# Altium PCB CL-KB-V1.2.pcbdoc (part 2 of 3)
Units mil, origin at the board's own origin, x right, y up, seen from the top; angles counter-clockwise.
Board outline 3269.95 x 5989.25 mil, 2 copper layers (Top Layer, Bottom Layer); 76 components, 86 nets, 398 pads, 855 vias.
Unrouted connection lines stored in the file: 1.
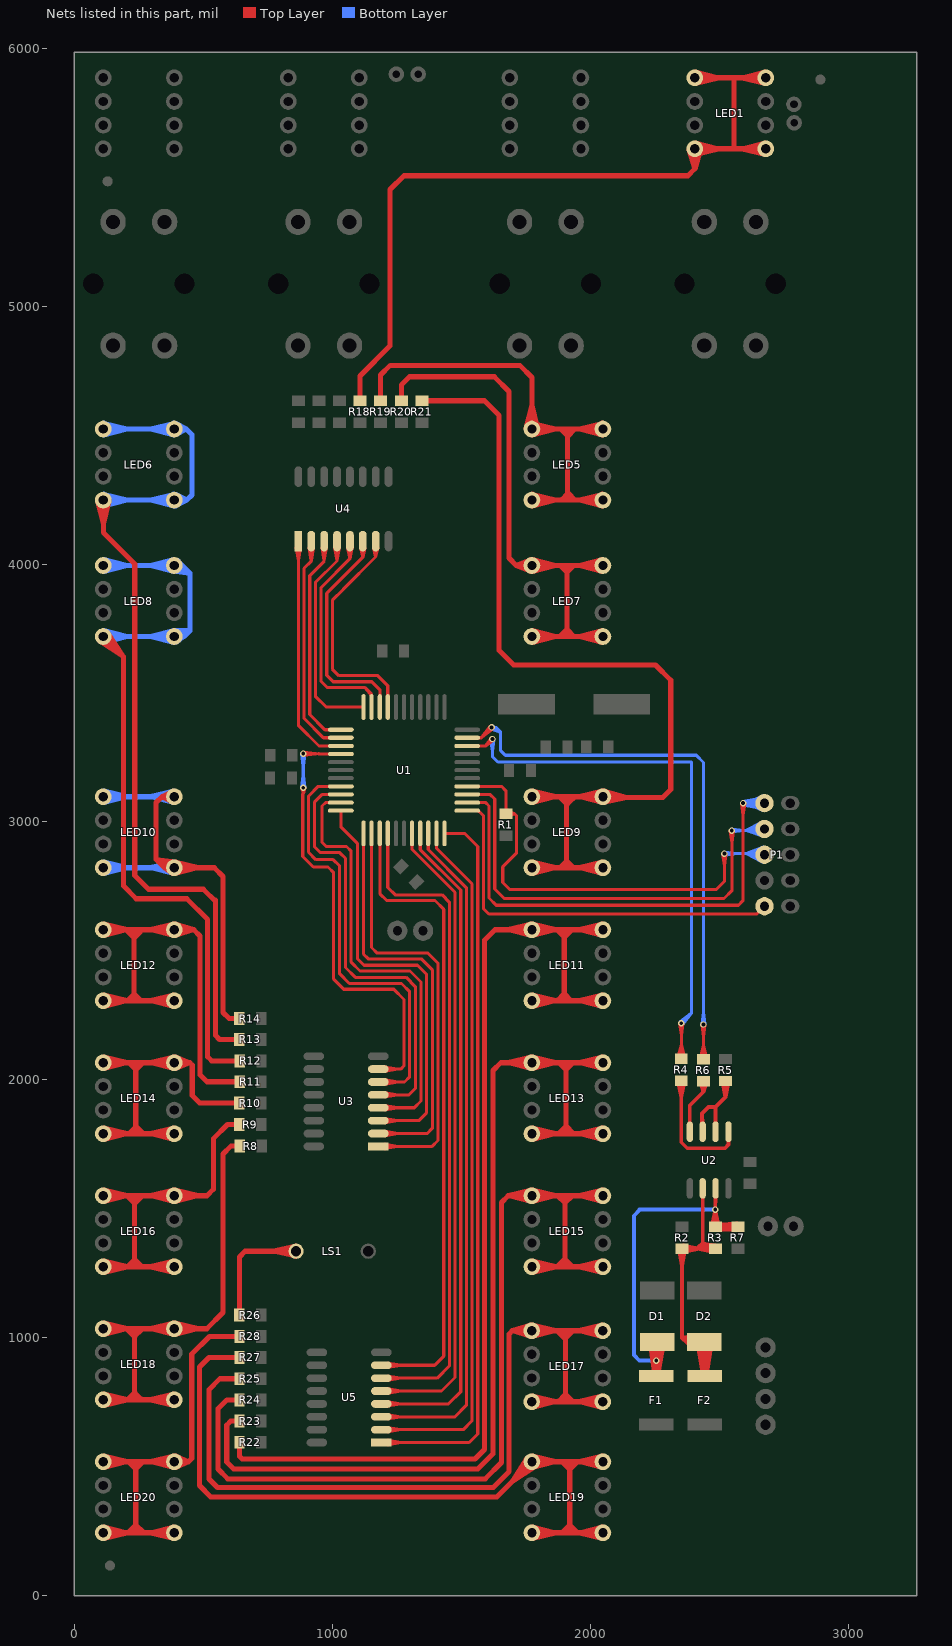
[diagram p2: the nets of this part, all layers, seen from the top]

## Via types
v1: diameter 25, hole 15, Top Layer to Bottom Layer, tented both sides, 855 vias

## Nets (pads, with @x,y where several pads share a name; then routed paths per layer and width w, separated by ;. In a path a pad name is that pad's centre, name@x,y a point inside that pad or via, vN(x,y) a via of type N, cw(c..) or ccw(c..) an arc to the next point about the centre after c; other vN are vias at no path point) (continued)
LEDK4: LED1.K R18.1 | length 4053.9
  Top Layer w20: R18.1@1106.15,4634.52 1106.15,4731.15 1223,4848 1223,5454 1277,5508 2379,5508 2405.48,5534.48 ; LED1.K@2383.22,5608.95 2405.48,5534.48 ; LED1.K@2405.48,5887.8 LED1.K@2681.07,5887.8 ; LED1.K@2408.22,5589.87 2497.98,5612.2 LED1.K@2408.22,5634.54 ; LED1.K@2408.22,5865.46 2497.98,5887.8 LED1.K@2408.22,5910.13 ; LED1.K@2427.74,5608.95 2405.48,5534.48 ; 2557,5612.2 2557,5887.8 ; LED1.K@2678.33,5589.87 2588.57,5612.2 ; LED1.K@2678.33,5634.54 2588.57,5612.2 ; LED1.K@2678.33,5865.46 2588.57,5887.8 LED1.K@2678.33,5910.13 ; 2405.48,5534.48 LED1.K@2405.48,5612.2 ; 2405.48,5534.48 LED1.K@2405.48,5612.2 ; LED1.K@2405.48,5612.2 LED1.K@2681.07,5612.2 2588.57,5612.2
LEDK5: LED5.K R19.1 | length 2998.3
  Top Layer w20: R19.1@1185.88,4634.52 1185.88,4734 1223.88,4772 1726,4772 1773.2,4724.8 LED5.K@1773.2,4524.8 LED5.K@2048.79,4524.8 1956.29,4524.8 ; LED5.K@1750.86,4527.54 1773.2,4617.3 LED5.K@1795.53,4527.54 ; LED5.K@1773.2,4249.21 LED5.K@2048.79,4249.21 1956.29,4249.21 ; LED5.K@1775.93,4226.88 1865.7,4249.21 LED5.K@1775.93,4271.54 ; LED5.K@1775.93,4502.47 1865.7,4524.8 LED5.K@1775.93,4547.14 ; 1886,4524.8 1911,4499.8 ; 1888.8,4250.21 1913.8,4275.21 ; 1912,4249.21 1912,4522.8 ; 1912.8,4498 1937.8,4523 ; 1914.8,4274.41 1939.8,4249.41 ; LED5.K@2046.05,4226.88 1956.29,4249.21 ; LED5.K@2046.05,4271.54 1956.29,4249.21 ; LED5.K@2046.05,4502.47 1956.29,4524.8 ; LED5.K@2046.05,4547.14 1956.29,4524.8
LEDK6: LED7.K R20.1 | length 3338.5
  Top Layer w20: R20.1@1266.58,4634.52 1266.58,4696 1298.58,4728 1627,4728 1684,4671 1684,4024 1712.72,3995.28 ; LED7.K@1769.01,3973.17 1712.72,3995.28 ; LED7.K@1769.01,4017.38 1712.72,3995.28 ; LED7.K@1773.2,3719.68 LED7.K@2048.79,3719.68 1956.29,3719.68 ; LED7.K@1773.2,3995.28 1712.72,3995.28 ; LED7.K@1775.93,3697.35 1865.7,3719.68 LED7.K@1775.93,3742.02 ; LED7.K@1775.93,3972.94 1865.7,3995.28 LED7.K@1775.93,4017.61 ; 1884,3994.8 1909,3969.8 ; 1884.2,3723 1909.2,3748 ; 1910,3719.68 1910,3995.28 ; 1910,3970 1935,3995 ; 1911,3745.2 1936,3720.2 ; LED7.K@2046.05,3697.35 1956.29,3719.68 ; LED7.K@2046.05,3742.02 1956.29,3719.68 ; LED7.K@2046.05,3972.94 1956.29,3995.28 ; LED7.K@2046.05,4017.61 1956.29,3995.28 ; 1712.72,3995.28 LED7.K@2048.79,3995.28 1956.29,3995.28
LEDK7: LED9.K R21.1 | length 4901.7
  Top Layer w20: R21.1@1346.31,4634.52 1589.48,4634.52 1646,4578 1646,3666 1703,3609 2253,3609 2312,3550 2312,3126 2281,3095 2051.82,3095 LED9.K@2048.79,3098.03 ; R21.1@1351.31,4634.52 1431.31,4634.52 ; LED9.K@1773.2,2822.44 LED9.K@2048.79,2822.44 1956.29,2822.44 ; LED9.K@1773.2,3098.03 LED9.K@2048.79,3098.03 ; LED9.K@1775.93,2800.11 1865.7,2822.44 LED9.K@1775.93,2844.77 ; LED9.K@1775.93,3075.7 1865.7,3098.03 LED9.K@1775.93,3120.36 ; 1882,3097.23 1907,3072.23 ; 1883.8,2823.44 1908.8,2848.44 ; 1908,2822.44 1908,3098.03 ; 1908.8,3067 1933.8,3092 ; 1909.8,2847.64 1934.8,2822.64 ; LED9.K@2046.05,2800.11 1956.29,2822.44 ; LED9.K@2046.05,2844.77 1956.29,2822.44 ; LED9.K@2046.05,3075.7 1956.29,3098.03 ; LED9.K@2046.05,3120.36 1956.29,3098.03 ; LED9.K@2050.79,3075.62 2141.4,3095 ; LED9.K@2052.25,3120.26 2141.4,3095 ; 1956.29,3098.03 LED9.K@2048.79,3098.03 ; LED9.K@2048.79,3098.03 2141.4,3095
LEDK8: LED18.K R8.1 | length 3022
  Top Layer w20: LED18.K@110.2,757.87 LED18.K@385.8,757.87 293.3,757.87 ; LED18.K@110.2,1033.46 511.46,1033.46 574,1096 574,1711 605,1742 ; LED18.K@112.94,735.54 202.7,757.87 LED18.K@112.94,780.21 ; LED18.K@112.94,1011.13 202.7,1033.46 LED18.K@112.94,1055.8 ; 205,1028.8 230,1003.8 ; 206.2,759.2 231.2,784.2 ; 229,1033.46 231,1031.46 231,757.87 ; 231.8,1004 256.8,1029 ; 232,785.2 257,760.2 ; LED18.K@383.06,735.54 293.3,757.87 ; LED18.K@383.06,780.21 293.3,757.87 ; LED18.K@383.06,1011.13 293.3,1033.46 ; LED18.K@383.06,1055.8 293.3,1033.46 ; LED18.K@385.8,1033.46 293.3,1033.46 ; LED18.K@388.53,1011.13 478.3,1033.46 LED18.K@388.53,1055.8 ; 605,1742 R8.1@640,1742 605,1742
LEDK9: LED16.K R9.1 | length 2607.3
  Top Layer w20: LED16.K@110.2,1274.02 LED16.K@385.8,1274.02 293.3,1274.02 ; LED16.K@110.2,1549.61 512,1549.61 537,1574.61 537,1771 591.54,1825.54 ; LED16.K@112.94,1251.68 202.7,1274.02 LED16.K@112.94,1296.35 ; LED16.K@112.94,1527.27 202.7,1549.61 LED16.K@112.94,1571.94 ; 205.8,1545.8 230.8,1520.8 ; 206.2,1276.2 231.2,1301.2 ; 227,1549.61 231,1545.61 231,1274.02 ; 231.8,1520 256.8,1545 ; 232,1302.2 257,1277.2 ; LED16.K@383.06,1251.68 293.3,1274.02 ; LED16.K@383.06,1296.35 293.3,1274.02 ; LED16.K@383.06,1527.27 293.3,1549.61 ; LED16.K@383.06,1571.94 293.3,1549.61 ; LED16.K@385.8,1549.61 293.3,1549.61 ; LED16.K@388.53,1527.27 478.3,1549.61 LED16.K@388.53,1571.94 ; 591.54,1825.54 R9.1@637.75,1825.54 591.54,1825.54
LEDK10: LED14.K R10.1 | length 2476.4
  Top Layer w20: LED14.K@110.2,1790.16 LED14.K@385.8,1790.16 293.3,1790.16 ; LED14.K@110.2,2065.75 445.25,2065.75 ; LED14.K@112.94,1767.82 202.7,1790.16 LED14.K@112.94,1812.49 ; LED14.K@112.94,2043.41 202.7,2065.75 LED14.K@112.94,2088.08 ; 210,2065.8 235,2040.8 ; 211.2,1792.2 236.2,1817.2 ; 236,1792.16 236,2065.75 ; 236.8,2039 261.8,2064 ; 237,1818.2 262,1793.2 ; LED14.K@383.06,1767.82 293.3,1790.16 ; LED14.K@383.06,1812.49 293.3,1790.16 ; LED14.K@383.06,2043.41 293.3,2065.75 ; LED14.K@383.06,2088.08 293.3,2065.75 ; LED14.K@385.8,2065.75 293.3,2065.75 ; LED14.K@390.05,2043.65 445.25,2065.75 ; LED14.K@390.05,2087.84 445.25,2065.75 ; 558,1909 R10.1@638,1909 484,1909 455,1938 455,2056 445.25,2065.75
LEDK11: LED12.K R11.1 | length 2934.1
  Top Layer w20: LED12.K@110.2,2306.3 LED12.K@385.8,2306.3 293.3,2306.3 ; LED12.K@110.2,2581.89 461.11,2581.89 ; LED12.K@112.94,2283.97 202.7,2306.3 LED12.K@112.94,2328.63 ; LED12.K@112.94,2559.56 202.7,2581.89 LED12.K@112.94,2604.22 ; 203.8,2575.8 228.8,2550.8 ; 204.2,2306.2 229.2,2331.2 ; 229,2306.3 229,2578.89 ; 229.8,2550 254.8,2575 ; 230,2332.2 255,2307.2 ; LED12.K@383.06,2283.97 293.3,2306.3 ; LED12.K@383.06,2328.63 293.3,2306.3 ; LED12.K@383.06,2559.56 293.3,2581.89 ; LED12.K@383.06,2604.22 293.3,2581.89 ; LED12.K@385.8,2581.89 293.3,2581.89 ; LED12.K@389.16,2559.64 461.11,2581.89 ; LED12.K@389.16,2604.14 461.11,2581.89 ; 559,1992 R11.1@639,1992 512,1992 485,2019 485,2558 461.11,2581.89
LEDK12: LED8.K R12.1 | length 4761.3
  Top Layer w20: LED8.K@96.07,3702.18 185.13,3644.76 LED8.K@127.71,3733.82 ; LED8.K@110.2,3719.68 189,3640.89 189,2751 238,2702 434,2702 515,2621 515,2089 531,2073 R12.1@639,2073 559,2073
  Bottom Layer w20: LED8.K@110.2,3719.68 423.68,3719.68 ; LED8.K@110.2,3995.28 415.72,3995.28 446,3965 ; LED8.K@112.94,3697.35 202.7,3719.68 LED8.K@112.94,3742.02 ; LED8.K@112.94,3972.94 202.7,3995.28 LED8.K@112.94,4017.61 ; LED8.K@379.18,3973.77 446,3965 ; LED8.K@381.79,3741.83 446,3742 ; LED8.K@383.06,3697.35 293.3,3719.68 ; LED8.K@383.06,3742.02 293.3,3719.68 ; LED8.K@383.06,3972.94 293.3,3995.28 ; LED8.K@383.06,4017.61 293.3,3995.28 ; LED8.K@397.19,3700.28 446,3742 ; LED8.K@399.12,4013.41 446,3965 ; 293.3,3719.68 LED8.K@385.8,3719.68 ; 293.3,3995.28 LED8.K@385.8,3995.28 446,3965 ; LED8.K@385.8,3719.68 446,3742 ; LED8.K@385.8,3719.68 423.68,3719.68 ; 423.68,3719.68 446,3742 ; 423.68,3719.68 392.48,3741.17 423.68,3719.68 ; 423.68,3719.68 392.48,3698.2 423.68,3719.68 ; 446,3742 446,3965
LEDK13: LED6.K R13.1 | length 4893.7
  Top Layer w20: LED6.K@87.87,4246.48 110.2,4156.71 ; LED6.K@132.54,4246.48 110.2,4156.71 ; 545,2692 498,2739 285,2739 232,2792 232,4001 110.2,4122.8 LED6.K@110.2,4249.21 110.2,4156.71 ; 545,2696 545,2172 561,2156 ; 561,2156 R13.1@638,2156 561,2156
  Bottom Layer w20: LED6.K@110.2,4249.21 434.21,4249.21 ; LED6.K@110.2,4524.8 432.2,4524.8 ; LED6.K@112.94,4226.88 202.7,4249.21 LED6.K@112.94,4271.54 ; LED6.K@112.94,4502.47 202.7,4524.8 LED6.K@112.94,4547.14 ; LED6.K@383.06,4226.88 293.3,4249.21 ; LED6.K@383.06,4271.54 293.3,4249.21 ; LED6.K@383.06,4502.47 293.3,4524.8 ; LED6.K@383.06,4547.14 293.3,4524.8 ; LED6.K@385.8,4249.21 293.3,4249.21 ; LED6.K@385.8,4524.8 293.3,4524.8 ; LED6.K@391.02,4227.33 434.21,4249.21 ; LED6.K@391.02,4271.1 434.21,4249.21 ; LED6.K@391.25,4502.97 432.2,4524.8 ; LED6.K@391.25,4546.63 432.2,4524.8 ; 432.2,4524.8 454,4503 454,4269 434.21,4249.21
LEDK14: LED10.K R14.1 | length 3494.7
  Top Layer w20: LED10.K@373.54,2803.57 315,2855 ; LED10.K@380.5,3076.16 338.03,3098.03 ; LED10.K@380.5,3119.9 338.03,3098.03 ; LED10.K@388.53,2800.11 478.3,2822.44 LED10.K@388.53,2844.77 ; LED10.K@392.15,2844.03 315,2855 ; 315,2855 315,3075 338.03,3098.03 ; 315,2855 347.56,2822.44 ; 315,2855 LED10.K@385.8,2822.44 ; 338.03,3098.03 LED10.K@385.8,3098.03 338.03,3098.03 ; 347.56,2822.44 540.56,2822.44 575,2788 575,2261 599,2237 ; 347.56,2822.44 379.18,2800.94 347.56,2822.44 ; 347.56,2822.44 379.18,2843.94 347.56,2822.44 ; 347.56,2822.44 LED10.K@385.8,2822.44 ; 347.56,2822.44 LED10.K@385.8,2822.44 ; 599,2237 R14.1@638,2237 599,2237
  Bottom Layer w20: LED10.K@110.2,2822.44 LED10.K@385.8,2822.44 293.3,2822.44 ; LED10.K@110.2,3098.03 LED10.K@385.8,3098.03 293.3,3098.03 ; LED10.K@112.94,2800.11 202.7,2822.44 LED10.K@112.94,2844.77 ; LED10.K@112.94,3075.7 202.7,3098.03 LED10.K@112.94,3120.36 ; LED10.K@383.06,2800.11 293.3,2822.44 ; LED10.K@383.06,2844.77 293.3,2822.44 ; LED10.K@383.06,3075.7 293.3,3098.03 ; LED10.K@383.06,3120.36 293.3,3098.03
LEDK15: LED11.K R22.1 | length 5421.4
  Top Layer w20: R22.1@638.45,588.17 638.45,538.55 ; R22.1@638.45,593.17 638.45,538.55 ; LED11.K@1770.43,2559.56 1680.7,2582 ; LED11.K@1770.49,2604.23 1680.7,2582 ; LED11.K@1773.2,2306.3 LED11.K@2048.79,2306.3 1956.29,2306.3 ; LED11.K@1775.93,2283.97 1865.7,2306.3 LED11.K@1775.93,2328.63 ; LED11.K@1775.93,2559.56 1865.7,2581.89 LED11.K@1775.93,2604.22 ; 1873,2580.8 1898,2555.8 ; 1873.2,2308 1898.2,2333 ; 1899,2307.3 1899,2581.89 ; 1899.2,2332.2 1924.2,2307.2 ; 1899.8,2554 1924.8,2579 ; LED11.K@2046.05,2283.97 1956.29,2306.3 ; LED11.K@2046.05,2328.63 1956.29,2306.3 ; LED11.K@2046.05,2559.56 1956.29,2581.89 ; LED11.K@2046.05,2604.22 1956.29,2581.89 ; 638.45,538.55 649,528 1552,528 1589,565 1589,2541 1630,2582 1773.09,2582 LED11.K@1773.2,2581.89 ; 1680.7,2582 LED11.K@1773.2,2581.89 ; LED11.K@1773.2,2581.89 LED11.K@2048.79,2581.89 1956.29,2581.89
LEDK16: LED13.K R23.1 | length 5120.9
  Top Layer w20: LED13.K@1770.46,2043.41 1680.7,2065.75 ; LED13.K@1770.46,2088.08 1680.7,2065.75 ; LED13.K@1773.2,1790.16 LED13.K@2048.79,1790.16 1956.29,1790.16 ; LED13.K@1773.2,2065.75 1680.7,2065.75 ; LED13.K@1775.93,1767.82 1865.7,1790.16 LED13.K@1775.93,1812.49 ; LED13.K@1775.93,2043.41 1865.7,2065.75 LED13.K@1775.93,2088.08 ; 1880,2064.8 1905,2039.8 ; 1880.2,1793 1905.2,1818 ; 1906,1792.16 1906,2065.75 ; 1906.8,2039 1931.8,2064 ; 1907,1818.2 1932,1793.2 ; LED13.K@2046.05,1767.82 1956.29,1790.16 ; LED13.K@2046.05,1812.49 1956.29,1790.16 ; LED13.K@2046.05,2043.41 1956.29,2065.75 ; LED13.K@2046.05,2088.08 1956.29,2065.75 ; 604.87,674.87 589,659 589,516 616,489 1563,489 1622,548 1622,2035 1652.75,2065.75 LED13.K@2048.79,2065.75 1956.29,2065.75 ; 604.87,674.87 R23.1@638.45,674.87 604.87,674.87
LEDK17: LED15.K R24.1 | length 4826.7
  Top Layer w20: LED15.K@1770.43,1527.28 1681.61,1549.61 ; LED15.K@1770.43,1571.94 1681.61,1549.61 ; LED15.K@1773.2,1274.02 LED15.K@2048.79,1274.02 1956.29,1274.02 ; LED15.K@1773.2,1549.61 1681.61,1549.61 ; LED15.K@1775.93,1251.68 1865.7,1274.02 LED15.K@1775.93,1296.35 ; LED15.K@1775.93,1527.27 1865.7,1549.61 LED15.K@1775.93,1571.94 ; 1876.2,1279 1901.2,1304 ; 1877,1547 1902,1522 1927,1547 ; 1902,1276.02 1902,1549.61 ; 1902.2,1303.2 1927.2,1278.2 ; LED15.K@2046.05,1251.68 1956.29,1274.02 ; LED15.K@2046.05,1296.35 1956.29,1274.02 ; LED15.K@2046.05,1527.27 1956.29,1549.61 ; LED15.K@2046.05,1571.94 1956.29,1549.61 ; 589.54,757.55 555,723 555,489 593,451 1592,451 1655,514 1655,1523 1681.61,1549.61 ; 589.54,757.55 R24.1@638.45,757.55 589.54,757.55 ; 1681.61,1549.61 LED15.K@2048.79,1549.61 1956.29,1549.61
LEDK18: LED17.K R25.1 | length 4507.5
  Top Layer w20: LED17.K@1768.83,1003.55 1697.2,1025.8 ; LED17.K@1768.83,1048.04 1697.2,1025.8 ; LED17.K@1772.2,750.2 LED17.K@2047.8,750.2 1955.3,750.2 ; LED17.K@1772.2,1025.8 1697.2,1025.8 ; LED17.K@1774.94,727.87 1864.7,750.2 LED17.K@1774.94,772.54 ; LED17.K@1774.94,1003.46 1864.7,1025.8 LED17.K@1774.94,1048.13 ; 1877,1019.8 1902,994.8 ; 1877.2,752 1902.2,777 ; 1902.8,995.8 1927.8,1020.8 ; 1903,751.2 1903,1025.8 ; 1904,778.2 1929,753.2 ; LED17.K@2045.06,727.87 1955.3,750.2 ; LED17.K@2045.06,772.54 1955.3,750.2 ; LED17.K@2045.06,1003.46 1955.3,1025.8 ; LED17.K@2045.06,1048.13 1955.3,1025.8 ; 562.24,839.24 520,797 520,450 553,417 1623,417 1685,479 1685,1013.59 1697.2,1025.8 ; 562.24,839.24 R25.1@638.45,839.24 562.24,839.24 ; 1697.2,1025.8 LED17.K@2047.8,1025.8 1955.3,1025.8
LEDK19: LED19.K R27.1 | length 4286.7
  Top Layer w20: 558.45,921.92 R27.1@638.45,921.92 520,921.92 483,884.92 483,425 527,381 1636.87,381 LED19.K@1773.2,517.32 ; LED19.K@1755.69,531.45 1698.27,442.4 ; LED19.K@1773.2,241.73 LED19.K@2048.79,241.73 1956.29,241.73 ; LED19.K@1775.93,219.4 1865.7,241.73 LED19.K@1775.93,264.06 ; LED19.K@1775.93,494.99 1865.7,517.32 LED19.K@1775.93,539.66 ; LED19.K@1787.33,499.81 1698.27,442.4 ; 1894,513.8 1919,488.8 ; 1894.2,245 1919.2,270 ; 1920,241.73 1920,517.32 ; 1920.8,489 1945.8,514 ; 1921,270.2 1946,245.2 ; LED19.K@2046.05,219.4 1956.29,241.73 ; LED19.K@2046.05,264.06 1956.29,241.73 ; LED19.K@2046.05,494.99 1956.29,517.32 ; LED19.K@2046.05,539.66 1956.29,517.32 ; 1698.27,442.4 LED19.K@1773.2,517.32 ; LED19.K@1773.2,517.32 LED19.K@2048.79,517.32 1956.29,517.32
LEDK20: LED20.K R28.1 | length 2774
  Top Layer w20: LED20.K@110.2,241.73 LED20.K@385.8,241.73 293.3,241.73 ; LED20.K@110.2,517.32 440.32,517.32 ; LED20.K@112.94,219.4 202.7,241.73 LED20.K@112.94,264.06 ; LED20.K@112.94,494.99 202.7,517.32 LED20.K@112.94,539.66 ; 210,515.8 235,490.8 ; 210.2,246 235.2,271 ; 236,241.73 236,516.32 237,517.32 ; 236.8,491 261.8,516 ; 237,271.2 262,246.2 ; LED20.K@383.06,219.4 293.3,241.73 ; LED20.K@383.06,264.06 293.3,241.73 ; LED20.K@383.06,494.99 293.3,517.32 ; LED20.K@383.06,539.66 293.3,517.32 ; LED20.K@385.8,517.32 293.3,517.32 ; LED20.K@390.44,495.31 440.32,517.32 ; LED20.K@390.44,539.34 440.32,517.32 ; 558.45,1003.61 R28.1@638.45,1003.61 521.61,1003.61 453,935 453,530 440.32,517.32
LOUT1: U1.35 U3.1 | length 1863.8
  Top Layer w12: 1151,2870 U1.35@1151,2914 ; U1.35@1151,2967 1151,2513 1173,2491 1370,2491 1409,2452 1409,1764 1386,1741 U3.1@1177,1741 ; U3.1@1202,1741 1253,1741 ; U3.1@1202.79,1732.04 1253,1741 ; U3.1@1202.79,1749.96 1253,1741
LOUT2: U1.34 U3.2 | length 1791.6
  Top Layer w12: 1120,2870 U1.34@1120,2914 ; U1.34@1120,2956 1120,2487 1138,2469 1344,2469 1387,2426 1387,1811 1367,1791 U3.2@1177,1791 ; U3.2@1202,1791 1253,1791 ; U3.2@1202.79,1782.04 1253,1791 ; U3.2@1202.79,1799.96 1253,1791
LOUT3: U1.33 U3.3 | length 1829
  Top Layer w12: 1032,3000 U1.33@1032,3044 1032,2981 1096,2917 1096,2470 1122,2444 1329,2444 1365,2408 1365,1872 1334,1841 U3.3@1177,1841 ; U3.3@1202,1841 1253,1841 ; U3.3@1202.79,1832.04 1253,1841 ; U3.3@1202.79,1849.96 1253,1841
LOUT4: U1.32 U3.4 | length 1890.1
  Top Layer w12: U1.32@990,3075 972,3075 ; U1.32@1032,3075 972,3075 ; U3.4@1177,1891 1317,1891 1343,1917 1343,2379 1300,2422 1106,2422 1072,2456 1072,2887 1054,2905 975,2905 959,2921 959,3062 972,3075 ; U3.4@1202,1891 1253,1891 ; U3.4@1202.79,1882.04 1253,1891 ; U3.4@1202.79,1899.96 1253,1891
LOUT5: U1.31 U3.5 | length 1884.9
  Top Layer w12: U1.31@990,3107 960,3107 ; U1.31@1032,3107 960,3107 ; U3.5@1177,1941 1296,1941 1321,1966 1321,2361 1285,2397 1088,2397 1050,2435 1050,2859 1028,2881 953,2881 929,2905 929,3076 960,3107 ; U3.5@1202,1941 1253,1941 ; U3.5@1202.79,1932.04 1253,1941 ; U3.5@1202.79,1949.96 1253,1941
LOUT6: U1.30 U3.6 | length 1878.4
  Top Layer w12: 946,3138 U1.30@990,3138 ; U1.30@1032,3138 944,3138 906,3100 906,2883 935,2854 1002,2854 1027,2829 1027,2411 1065,2373 1267,2373 1299,2341 1299,2011 1279,1991 U3.6@1177,1991 ; U3.6@1202,1991 1253,1991 ; U3.6@1202.79,1982.04 1253,1991 ; U3.6@1202.79,1999.96 1253,1991
LOUT7: U1.26 U3.7 | length 2375.2
  Top Layer w12: v1@879.57,3132.03 886,3111.11 ; v1(886,3265) U1.26@1032,3264 ; v1@886.39,3258.51 934.5,3264.67 v1@886.48,3271.48 ; v1@892.43,3132.03 886,3111.11 ; 946,3264.59 U1.26@990,3264 ; U3.7@1177,2041 1264,2041 1277,2054 1277,2311 1237,2351 1043,2351 1004,2390 1004,2803 982,2825 925,2825 884,2866 884,3109.11 886,3111.11 ; U3.7@1202,2041 1253,2041 ; U3.7@1202.79,2032.04 1253,2041 ; U3.7@1202.79,2049.96 1253,2041 ; 886,3111.11 v1(886,3133) 886,3111.11
  Bottom Layer w12: v1@879.51,3133.44 886,3181.5 v1@892.49,3133.44 ; v1@879.51,3264.56 886,3216.5 ; v1(886,3133) v1(886,3265) 886,3216.5 ; v1@892.49,3264.56 886,3216.5
LOUT8: U1.25 U4.1 | length 1109
  Top Layer w12: U4.1@858.04,4064.21 867,4014 ; U4.1@867,4065 867,4014 ; U4.1@867,4090 867,3375.11 947.11,3295 ; U4.1@875.96,4064.21 867,4014 ; U1.25@990,3295 947.11,3295 ; U1.25@1032,3295 947.11,3295
LOUT9: U1.24 U4.2 | length 1052.5
  Top Layer w12: U4.2@908.04,4064.21 917,4014 ; U4.2@917,4065 917,4014 ; U4.2@917,4090 917,4012 889,3984 889,3402.11 964.11,3327 ; U4.2@925.96,4064.21 917,4014 ; U1.24@990,3327 964.11,3327 ; U1.24@1032,3327 964.11,3327
LOUT10: U1.23 U4.3 | length 1021.6
  Top Layer w12: U4.3@958.04,4064.21 967,4014 ; U4.3@967,4065 967,4014 ; U4.3@967,4097 967,4012 911,3956 911,3417 970,3358 ; U4.3@975.96,4064.21 967,4014 ; U1.23@990,3358 970,3358 ; U1.23@1032,3358 970,3358
LOUT11: U1.22 U4.4 | length 1038.2
  Top Layer w12: U4.4@1008.04,4064.21 1017,4014 ; U4.4@1017,4065 1017,4014 ; U4.4@1017,4090 1017,4013 933,3929 933,3488 975,3446 U1.22@1120,3446 1076,3446 ; U4.4@1025.96,4064.21 1017,4014
LOUT12: U1.21 U4.5 | length 1048
  Top Layer w12: U4.5@1058.05,4064.08 1067,4021 ; U4.5@1067,4065 1067,4021 ; U4.5@1067,4090 1067,4021 ; U4.5@1075.95,4064.08 1067,4021 ; 1127.34,3520.66 U1.21@1151,3488 ; U1.21@1151,3446 1151,3497 ; 1067,4021 955,3909 955,3546 979,3522 1126,3522 1151,3497 ; U1.21@1151,3488 1151,3497 ; U1.21@1151,3488 1151,3497
LOUT13: U1.20 U4.6 | length 1025.2
  Top Layer w12: U4.6@1108.06,4063.93 1117,4027 ; U4.6@1117,4065 1117,4027 ; U4.6@1117,4101 1117,4027 ; U4.6@1125.94,4063.93 1117,4027 ; U1.20@1183,3446 1183,3513 ; U1.20@1183,3488 1183,3513 ; 1117,4027 977,3887 977,3569 1002,3544 1152,3544 1183,3513
LOUT14: U1.19 U4.7 | length 1042.7
  Top Layer w12: U4.7@1158.04,4064.15 1166,4028 ; U4.7@1166,4089 1166,4028 ; U4.7@1167,4065 1166,4028 ; U4.7@1167,4089 U4.7@1167,4090 ; U4.7@1175.9,4063.66 1166,4028 ; U1.19@1214,3446 1214,3529 ; U1.19@1214,3488 1214,3529 ; 1166,4028 1043,3905 1043,3904 999,3860 999,3593 1024,3568 1175,3568 1214,3529
LOUT15: U1.44 U5.1 | length 2970.9
  Top Layer w12: U5.1@1188.98,591.73 1529.73,591.73 1563,625 1563,2905 1512,2956 U1.44@1434,2956 ; U5.1@1213.98,591.73 1264.98,591.73 ; U5.1@1214.77,582.77 1264.98,591.73 ; U5.1@1214.77,600.7 1264.98,591.73
LOUT16: U1.43 U5.2 | length 2872.4
  Top Layer w12: U5.2@1188.98,641.73 1506.73,641.73 1541,676 1541,2760 1403,2898 ; U5.2@1213.98,641.73 1264.98,641.73 ; U5.2@1214.77,632.77 1264.98,641.73 ; U5.2@1214.77,650.7 1264.98,641.73 ; U1.43@1403,2914 1403,2898 ; U1.43@1403,2956 1403,2898
LOUT17: U1.42 U5.3 | length 2803.7
  Top Layer w12: U5.3@1188.98,691.73 1474.73,691.73 1519,736 1519,2744.96 1371,2892.96 ; U5.3@1213.98,691.73 1264.98,691.73 ; U5.3@1214.77,682.77 1264.98,691.73 ; U5.3@1214.77,700.7 1264.98,691.73 ; U1.42@1371,2914 1371,2892.96 ; U1.42@1371,2956 1371,2892.96
LOUT18: U1.41 U5.4 | length 2733.8
  Top Layer w12: U5.4@1188.98,741.73 1449.73,741.73 1497,789 1497,2735.85 1340,2892.85 ; U5.4@1213.98,741.73 1264.98,741.73 ; U5.4@1214.77,732.77 1264.98,741.73 ; U5.4@1214.77,750.7 1264.98,741.73 ; U1.41@1340,2914 1340,2892.85 ; U1.41@1340,2956 1340,2892.85
LOUT19: U1.40 U5.5 | length 2662.1
  Top Layer w12: U5.5@1188.98,791.73 1422.73,791.73 1475,844 1475,2726.73 1308,2893.73 ; U5.5@1213.98,791.73 1264.98,791.73 ; U5.5@1214.77,782.77 1264.98,791.73 ; U5.5@1214.77,800.7 1264.98,791.73 ; U1.40@1308,2914 1308,2893.73 ; U1.40@1308,2956 1308,2893.73
LOUT20: U1.37 U5.6 | length 2753.2
  Top Layer w12: U5.6@1188.98,841.73 1405.73,841.73 1453,889 1453,2689 1425,2717 1243,2717 1214,2746 U1.37@1214,2956 ; U5.6@1213.98,841.73 1264.98,841.73 ; 1214,2870 U1.37@1214,2914 ; U5.6@1214.77,832.77 1264.98,841.73 ; U5.6@1214.77,850.7 1264.98,841.73
LOUT21: U1.36 U5.7 | length 2704.9
  Top Layer w12: U1.36@1182,2956 U1.36@1182,2966 ; 1183,2870 U1.36@1183,2914 ; U1.36@1183,2956 1183,2722 1210,2695 1397,2695 1431,2661 1431,927 1395.73,891.73 U5.7@1188.98,891.73 ; U5.7@1213.98,891.73 1264.98,891.73 ; U5.7@1214.77,882.77 1264.98,891.73 ; U5.7@1214.77,900.7 1264.98,891.73
MISO: P1.9 U1.2 | length 3297.6
  Top Layer w12: U1.2@1522,3075 1594,3075 ; U1.2@1564,3075 1594,3075 ; v1@2586.51,3072.7 2592,3024.46 ; v1@2592,3072 2592,2694 2575,2677 1635,2677 1607,2705 1607,3062 1594,3075 ; v1(2593,3073) 2592,3024.46 ; v1@2599.48,3072.43 2592,3024.46
  Bottom Layer w12: v1@2591.32,3066.72 2641.88,3056.56 ; v1@2591.32,3079.28 2641.88,3089.44 ; v1@2592.2,3066.55 P1.9@2642.24,3063.59 ; v1@2592.2,3079.45 P1.9@2642.24,3082.41 ; v1@2594.63,3066.71 P1.9@2642.24,3082.41 ; v1@2594.63,3079.29 P1.9@2642.24,3063.59 ; v1@2595.46,3066.98 2641.88,3089.44 ; v1@2595.46,3079.02 2641.88,3056.56 ; P1.9@2669.94,3044.2 v1@2604.57,3073 ; P1.9@2669.94,3101.8 v1@2604.57,3073 ; P1.9@2673.87,3055.7 v1@2604.57,3073 ; P1.9@2673.87,3090.3 v1@2604.57,3073 ; v1(2593,3073) P1.9@2676,3073 v1@2604.57,3073 ; v1(2593,3073) 2641.88,3089.44 ; v1(2593,3073) P1.9@2642.24,3082.41 ; v1(2593,3073) P1.9@2641.5,3073 ; v1(2593,3073) 2641.88,3056.56 ; v1(2593,3073) P1.9@2642.24,3063.59 ; P1.9@2641.5,3073 2593.44,3079.49 P1.9@2641.5,3073 ; P1.9@2641.5,3073 2593.44,3066.51 P1.9@2641.5,3073
MOSI: P1.1 U1.1 | length 1572.3
  Top Layer w12: U1.1@1522,3044 1566,3044 1585,3025 ; U1.1@1564,3044 1585,3025 ; P1.1@2676,2673 2646,2643 1606,2643 1585,2664 1585,3025
NetD1_K: D1.K F1.2 R3.1 R7.2 U2.7 | length 4331.8
  Top Layer w15: R3.1@2472.56,1430.2 2485,1494 R3.1@2497.44,1430.2 ; R3.1@2474.33,1439.27 v1(2485,1496) ; R3.1@2485,1438.5 v1(2485,1496) ; v1@2485,1492.99 2486,1550 v1(2485,1496) ; U2.7@2486,1578 2485,1577 R3.1@2485,1429 R7.2@2573,1429 ; R3.1@2490,1429 R7.2@2555,1429 ; R3.1@2491.2,1416.56 R7.2@2555,1429 ; R3.1@2491.2,1441.44 R7.2@2555,1429 ; R3.1@2495.67,1439.27 v1(2485,1496) ; R7.2@2564.91,1416.89 R3.1@2503.01,1439.14 ; R7.2@2564.91,1441.11 R3.1@2503.01,1418.86 ; R7.2@2568.74,1416.52 R3.1@2503.01,1418.86 ; R7.2@2568.74,1441.48 R3.1@2503.01,1439.14 ; R3.1@2503.01,1418.86 R7.2@2568,1429 ; R3.1@2503,1429 2566.8,1416.56 R3.1@2503,1429 ; R3.1@2503,1429 2566.8,1441.44 R3.1@2503,1429 ; R3.1@2503,1429 R7.2@2568,1429 ; R3.1@2503,1429 R7.2@2568,1429 ; R3.1@2503.01,1439.14 R7.2@2568,1429
  Top Layer w30: D1.K@2255.94,971.94 F1.2@2255.94,850.45 ; F1.2@2255.94,850.45 2275.73,962.74 v1(2255.94,910) ; F1.2@2255.94,850.45 2241.39,963.35 v1(2255.94,910) ; F1.2@2255.94,850.45 2258.57,964.05 v1(2255.94,910) ; F1.2@2255.94,850.45 v1(2255.94,910) ; F1.2@2255.94,850.45 v1(2255.94,910) ; F1.2@2255.94,850.45 v1(2255.94,910) ; F1.2@2255.94,850.45 v1(2255.94,910) ; F1.2@2255.94,856.65 2278.89,979.66 v1(2255.94,910) ; F1.2@2255.94,856.65 2239.03,980.64 v1(2255.94,910) ; F1.2@2255.94,856.65 D1.K@2259,981.75 v1(2255.94,910) ; F1.2@2255.94,856.65 v1(2255.94,910) ; F1.2@2255.94,856.65 v1(2255.94,910) ; F1.2@2255.94,856.65 v1(2255.94,910)
  Bottom Layer w15: 2190,1496 v1(2485,1496) 2427.5,1496 ; 2193,1496 2169,1472 2169,931 2190,910 v1(2255.94,910) 2198.44,910
NetD2_K: D2.K F2.2 R2.2 R3.2 U2.6 | length 3246.7
  Top Layer w15: R2.2@2343.56,1342.8 2356,1279 ; R2.2@2361,1344 2426,1344 ; R2.2@2362.2,1331.56 2426,1344 ; R2.2@2362.2,1356.44 2426,1344 ; R2.2@2368.44,1342.8 2356,1279 ; D2.K@2397.16,958.01 2356,998 ; D2.K@2406.22,970.22 2356,998 ; D2.K@2412.28,1009.22 2356,998 ; D2.K@2413.25,994.05 2356,998 ; 2418,1348 2436,1366 ; 2436,1345 U2.6@2436,1578 ; 2436,1493 U2.6@2436,1550 ; D2.K@2442.97,981.75 2372.25,981.75 ; R3.2@2473.33,1333.43 2435,1365 ; R3.2@2475.8,1332.23 2453,1347 ; R3.2@2478.49,1356.41 2453,1347 ; R3.2@2478.8,1331.56 2415,1344 ; R3.2@2478.8,1356.44 2415,1344 ; R3.2@2483.82,1355.9 2435,1365 ; R3.2@2485,1344 R2.2@2356,1344 ; 2356,998 R2.2@2356,1344 ; 2356,998 2372.25,981.75 ; 2356,998 D2.K@2411.04,981.75 ; 2356,1279 R2.2@2356,1344 ; 2372.25,981.75 2401.29,956.03 2372.25,981.75 ; 2372.25,981.75 2401.29,1007.46 2372.25,981.75 ; 2372.25,981.75 2409.03,969.41 2372.25,981.75 ; 2372.25,981.75 2409.03,994.08 2372.25,981.75 ; 2372.25,981.75 D2.K@2411.04,981.75 ; 2372.25,981.75 D2.K@2411.04,981.75 ; 2415,1344 R3.2@2480,1344 ; 2435,1365 2453,1347 ; 2435,1365 R3.2@2480,1344 ; 2453,1347 R3.2@2480,1344
  Top Layer w30: D2.K@2423.05,979.99 F2.2@2443.95,856.74 ; D2.K@2425.93,962.97 F2.2@2443.95,850.45 ; D2.K@2442.97,981.75 F2.2@2443.95,856.74 ; D2.K@2443.11,964.07 F2.2@2443.95,850.45 ; D2.K@2443.95,980.76 F2.2@2443.95,850.45 ; D2.K@2460.29,963.16 F2.2@2443.95,850.45 ; D2.K@2462.92,980.31 F2.2@2443.95,856.74
NetLS1_2: LS1.2 R26.2 | length 803.8
  Top Layer w20: R26.2@638.09,1086.29 638.09,1312.09 660.33,1334.33 LS1.2@858.26,1334.33 768.73,1334.33 ; R26.2@638.09,1091.29 638.09,1171.29 ; LS1.2@856.13,1314.92 768.73,1334.33 ; LS1.2@856.13,1353.74 768.73,1334.33
NetR4_1: R4.1 U2.1 | length 704.3
  Top Layer w15: R4.1@2340.56,1994.8 2353,1931 ; R4.1@2365.44,1994.8 2353,1931 ; U2.1@2536,1770 2536,1748 ; U2.1@2536,1798 2536,1748 ; 2353,1931 R4.1@2353,1996 2353,1757 2376,1734 2522,1734 2536,1748
NetR5_1: R5.1 U2.2 U2.3 | length 601.3
  Top Layer w12: R5.1@2525,1995 R5.1@2529,1991
  Top Layer w15: U2.3@2433,1836 2433,1869 ; U2.3@2436,1826 2433,1869 ; U2.2@2486,1798 2486,1894 ; U2.2@2486,1826 2486,1883 ; R5.1@2512.56,1993.74 2525,1933 ; R5.1@2537.44,1993.74 2525,1933 ; 2433,1869 2458,1894 2486,1894 ; 2486,1894 2525,1933 ; 2525,1933 R5.1@2525,1995 2525,1933
NetR6_1: R6.1 U2.4 | length 398
  Top Layer w15: U2.4@2386,1798 2386,1900 2439,1953 ; U2.4@2386,1826 2386,1883 ; R6.1@2426.65,1992.09 2439,1953 ; R6.1@2451.35,1992.09 2439,1953 ; 2439,1953 R6.1@2439,1994 2439,1953
RST: P1.5 R1.1 U1.4 | length 2450.8
  Top Layer w12: U1.4@1522,3138 1655,3138 1672,3121 R1.1@1672,3032 1705,3032 ; U1.4@1564,3138 1608,3138 ; R1.1@1677,3032 1705,3032 ; R1.1@1680.5,3018.44 1705,3032 ; R1.1@1680.5,3045.56 1705,3032 ; v1@2513.51,2876.56 2520,2828.5 ; v1@2526.49,2876.56 2520,2828.5 ; 1705,3032 1714,3023 1714,2880 1660,2826 1660,2765 1687,2738 2489,2738 2520,2769 v1(2520,2877) 2520,2828.5
  Bottom Layer w12: v1(2520,2877) 2672,2877 P1.5@2676,2873 2604.42,2877 ; v1@2520.44,2870.51 2568.5,2877 v1@2520.44,2883.49 ; P1.5@2668.36,2844.58 2604.42,2877 ; P1.5@2671.58,2902.1 2604.42,2877 ; P1.5@2672.92,2855.84 2604.42,2877 ; P1.5@2674.85,2890.39 2604.42,2877
RXD: R4.2 U1.9 | length 2781.4
  Top Layer w12: U1.9@1522,3295 1593,3295 ; U1.9@1564,3295 1593,3295 ; v1@1615.03,3326.19 1593,3295 ; v1@1624.19,3317.03 1593,3295 ; R4.2@2339.11,2082.75 2353,2137 R4.2@2366.89,2082.75 ; v1@2346.51,2218.56 2353,2170.5 ; R4.2@2353,2081 v1(2353,2219) 2353,2170.5 ; v1@2359.49,2218.56 2353,2170.5 ; 1593,3295 v1(1620,3322) 1593,3295
  Bottom Layer w12: v1@1613.51,3321.56 1620,3273.5 ; v1@1626.49,3321.56 1620,3273.5 ; v1@2348.69,2223.87 2390.96,2256.96 v1@2357.87,2214.69 ; v1(2353,2219) 2393,2259 2393,3233 1641,3233 1620,3254 v1(1620,3322) 1620,3273.5
SCK: P1.7 U1.3 | length 2421.9
  Top Layer w12: U1.3@1522,3107 1612,3107 1612,3106 1629,3089 1629,2740 1666,2703 2519,2703 2549,2733 v1(2549,2966.75) 2549,2918.25 ; U1.3@1564,3107 1608,3107 ; v1@2542.51,2966.31 2549,2918.25 ; v1@2555.49,2966.31 2549,2918.25
  Bottom Layer w12: v1(2549,2966.75) 2669.75,2966.75 P1.7@2676,2973 2604.22,2966.75 ; v1@2549.44,2960.26 2597.5,2966.75 v1@2549.44,2973.23 ; P1.7@2667.51,3001.18 2604.22,2966.75 ; P1.7@2672.4,2990.06 2604.22,2966.75 ; P1.7@2672.51,2943.77 2604.22,2966.75 ; P1.7@2675.4,2955.58 2604.22,2966.75
TXD: R6.2 U1.10 | length 2924.5
  Top Layer w12: U1.10@1522,3327 1577,3327 ; v1@1612.13,3371.31 1579.04,3329.04 ; v1@1621.31,3362.13 1579.04,3329.04 ; R6.2@2425.11,2080.75 2439,2135 R6.2@2452.89,2080.75 ; v1@2432.51,2213.56 2439,2165.5 ; R6.2@2439,2079 v1(2439,2214) 2439,2165.5 ; v1@2445.49,2213.56 2439,2165.5 ; 1577,3327 v1(1617,3367) 1579.04,3329.04 ; 1577,3327 1564,3327 1577,3327
  Bottom Layer w12: v1@1614.38,3361.05 1652,3348 ; v1@1620.56,3372.44 1652,3348 ; v1@2432.51,2214.44 2439,2262.5 v1@2445.49,2214.44 ; v1(2439,2214) 2439,3231 2411,3259 1670,3259 1652,3277 1652,3348 ; v1(1617,3367) 1633,3367 ; v1(1617,3367) 1652,3348 ; v1(1617,3367) 1633,3367 ; 1633,3367 1652,3348 ; 1633,3367 1618.32,3373.36 1633,3367 ; 1633,3367 1618.32,3360.64 1633,3367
